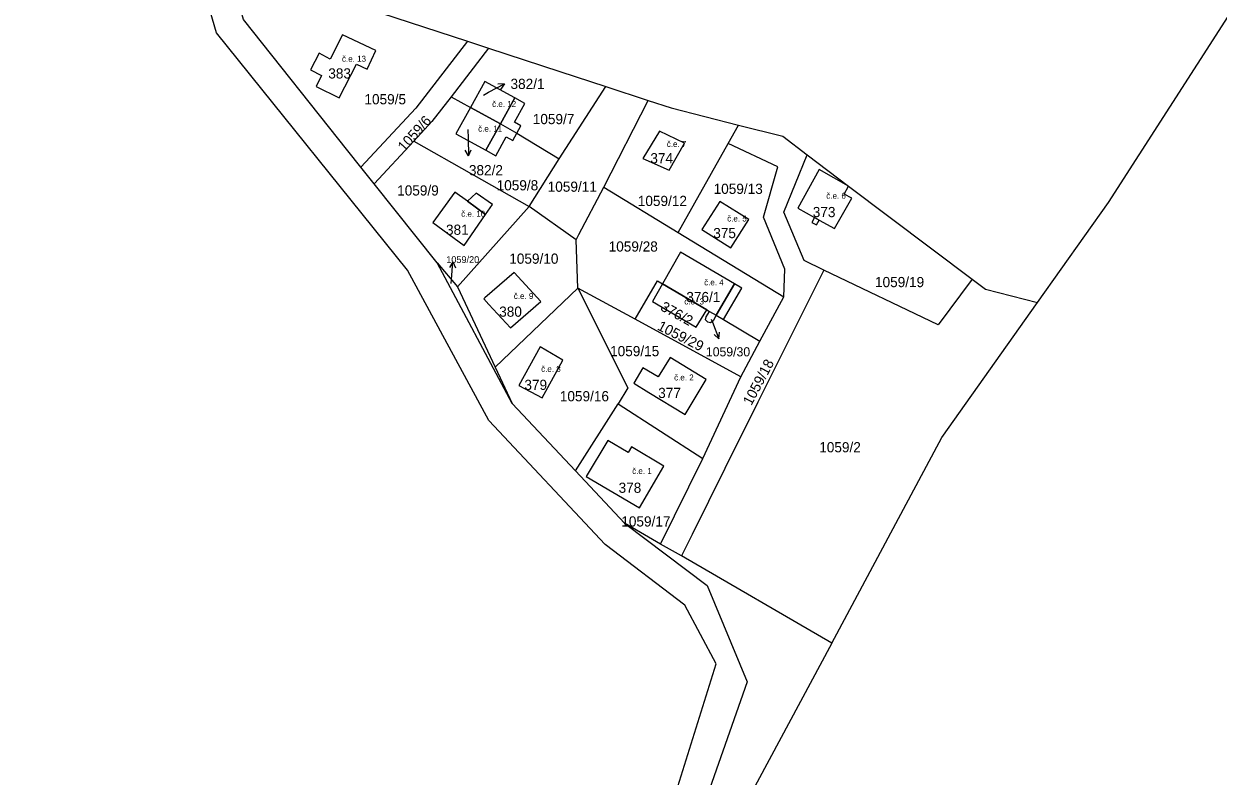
# Model space of a CAD drawing. Extents: x -887272 to -877616, y -1026687 to -1019819.
# Drawn here: x -884874.3 to -884674.7, y -1024745.1 to -1024619.5 of the extents above; entities that cross this region are included whole.
import ezdxf

# ---------------------------------------------------------------- set-up
doc = ezdxf.new("R2010")
doc.units = 0
for name, color, linetype in [('Definiční body', 7, 'Continuous'), ('Hranice parcel', 7, 'Continuous'), ('Parcelní čísla', 7, 'Continuous'), ('Polygon budovy', 7, 'Continuous'), ('Pop  PČ popisy', 7, 'Continuous'), ('Vnitřní kresba', 7, 'Continuous')]:
    doc.layers.add(name, color=color, linetype=linetype)

msp = doc.modelspace()

# ---------------------------------------------------------------- linework, layer by layer
at = {"layer": 'Hranice parcel'}
for p, q in [((-884814.72, -1024617.68), (-884800.18, -1024622.42)), ((-884796.65, -1024623.57), (-884802.91, -1024631.68)), ((-884800.18, -1024622.42), (-884796.65, -1024623.57)), ((-884802.91, -1024631.68), (-884799.68, -1024633.48)), ((-884784.84, -1024642.04), (-884777.08, -1024629.98)), ((-884777.08, -1024629.98), (-884769.96, -1024632.31)), ((-884777.38, -1024646.78), (-884769.96, -1024632.31)), ((-884791.94, -1024637.75), (-884784.84, -1024642.04)), ((-884756.59, -1024639.48), (-884754.87, -1024636.42)), ((-884809.16, -1024639.09), (-884815.78, -1024646.23)), ((-884809.16, -1024639.09), (-884789.89, -1024650)), ((-884764.95, -1024654.33), (-884756.59, -1024639.48)), ((-884815.78, -1024646.23), (-884818, -1024643.45)), ((-884789.89, -1024650), (-884784.84, -1024642.04)), ((-884805.24, -1024659.42), (-884815.78, -1024646.23)), ((-884777.38, -1024646.78), (-884764.95, -1024654.33)), ((-884704.9, -1024666.04), (-884693.07, -1024649.32)), ((-884801.87, -1024663.41), (-884789.89, -1024650)), ((-884782.02, -1024655.56), (-884789.89, -1024650)), ((-884781.74, -1024663.63), (-884782.02, -1024655.56)), ((-884764.95, -1024654.33), (-884747.32, -1024665.08)), ((-884792.7, -1024682.88), (-884805.24, -1024659.42)), ((-884805.24, -1024659.42), (-884801.87, -1024663.41)), ((-884801.87, -1024663.41), (-884795.58, -1024676.85)), ((-884795.58, -1024676.85), (-884781.74, -1024663.63)), ((-884772.16, -1024668.83), (-884781.74, -1024663.63)), ((-884767.59, -1024662.91), (-884760.18, -1024667.27)), ((-884715.82, -1024662.17), (-884713.6, -1024663.84)), ((-884751.3, -1024672.51), (-884747.32, -1024665.08)), ((-884713.6, -1024663.84), (-884704.9, -1024666.04)), ((-884760.18, -1024667.27), (-884759.75, -1024667.52)), ((-884759.75, -1024667.52), (-884758.62, -1024668.17)), ((-884754.48, -1024678.44), (-884772.16, -1024668.83)), ((-884758.62, -1024668.17), (-884757.41, -1024668.87)), ((-884757.41, -1024668.87), (-884751.3, -1024672.51)), ((-884754.48, -1024678.44), (-884751.3, -1024672.51)), ((-884795.58, -1024676.85), (-884792.7, -1024682.88)), ((-884760.84, -1024692.08), (-884754.48, -1024678.44)), ((-884782.13, -1024694.15), (-884792.7, -1024682.88)), ((-884782.13, -1024694.15), (-884774.99, -1024682.96)), ((-884774.99, -1024682.96), (-884760.84, -1024692.08)), ((-884767.91, -1024706.37), (-884760.84, -1024692.08)), ((-884773.92, -1024702.9), (-884782.13, -1024694.15)), ((-884767.91, -1024706.37), (-884773.92, -1024702.9)), ((-884764.44, -1024708.37), (-884767.91, -1024706.37)), ((-884739.28, -1024722.9), (-884764.44, -1024708.37))]:
    msp.add_line(p, q, dxfattribs=at)
for points in [[(-884872.76, -1024922.63), (-884842.58, -1024868.45), (-884811.61, -1024820.67), (-884781.27, -1024777.38), (-884766.7, -1024752.19), (-884758.6, -1024726.39), (-884763.88, -1024716.6), (-884777.17, -1024706.45), (-884796.59, -1024685.75), (-884810.2, -1024660.64), (-884842.12, -1024620.99), (-884851.29, -1024589.53), (-884865.18, -1024571.88), (-884874.31, -1024559.51)], [(-884693.07, -1024649.32), (-884667.92, -1024610.27), (-884632.54, -1024600.92)], [(-884818, -1024643.45), (-884820.18, -1024640.72), (-884837.62, -1024618.78), (-884838.76, -1024614.74)], [(-884818.7, -1024626.24), (-884816.96, -1024627.1), (-884815.47, -1024623.94), (-884821.07, -1024621.37), (-884823.12, -1024625.4), (-884824.97, -1024624.43), (-884826.44, -1024627.21), (-884824.57, -1024628.14), (-884825.47, -1024629.98), (-884821.65, -1024631.89), (-884818.7, -1024626.24)], [(-884800.18, -1024622.42), (-884808.81, -1024633.57), (-884818, -1024643.45)], [(-884796.65, -1024623.57), (-884784.74, -1024627.46), (-884777.08, -1024629.98)], [(-884791.94, -1024637.75), (-884791.26, -1024636.52), (-884792.35, -1024635.93), (-884790.62, -1024632.79), (-884792.28, -1024631.87), (-884797.27, -1024629.12), (-884799.68, -1024633.48)], [(-884802.91, -1024631.68), (-884806.14, -1024635.84), (-884809.16, -1024639.09)], [(-884799.68, -1024633.48), (-884802.1, -1024637.86), (-884797.1, -1024640.61), (-884795.44, -1024641.53), (-884793.7, -1024638.38), (-884792.62, -1024638.98), (-884791.94, -1024637.75)], [(-884799.68, -1024633.48), (-884794.69, -1024636.23), (-884791.94, -1024637.75)], [(-884769.96, -1024632.31), (-884766.16, -1024633.56), (-884754.87, -1024636.42)], [(-884770.9, -1024642.02), (-884766.5, -1024643.96), (-884763.9, -1024639.42), (-884768.1, -1024637.44), (-884770.9, -1024642.02)], [(-884754.87, -1024636.42), (-884747.48, -1024638.28), (-884743.39, -1024641.37)], [(-884747.32, -1024665.08), (-884747.15, -1024660.46), (-884750.73, -1024651.77), (-884748.29, -1024643.38), (-884756.59, -1024639.48)], [(-884740.63, -1024660.62), (-884743.92, -1024659.04), (-884747.32, -1024650.95), (-884743.39, -1024641.37)], [(-884743.39, -1024641.37), (-884736.49, -1024646.62), (-884715.82, -1024662.17)], [(-884736.49, -1024646.62), (-884741.4, -1024643.84), (-884744.98, -1024650.29), (-884742.18, -1024651.85), (-884742.64, -1024652.68), (-884741.87, -1024653.1), (-884741.41, -1024652.27), (-884738.86, -1024653.69), (-884735.97, -1024648.64), (-884737.23, -1024647.93), (-884736.49, -1024646.62)], [(-884796.02, -1024649.68), (-884798.72, -1024647.8), (-884800.16, -1024649.14), (-884802.32, -1024647.64), (-884805.96, -1024652.7), (-884800.72, -1024656.54), (-884797.18, -1024651.34), (-884796.02, -1024649.68)], [(-884782.02, -1024655.56), (-884781.56, -1024654.69), (-884777.38, -1024646.78)], [(-884758.03, -1024649.17), (-884761, -1024653.83), (-884756.17, -1024656.93), (-884753.17, -1024652.21), (-884758.03, -1024649.17)], [(-884757.41, -1024668.87), (-884754.35, -1024663.65), (-884755.54, -1024662.95), (-884764.57, -1024657.65), (-884767.59, -1024662.91)], [(-884797.47, -1024665.45), (-884796.62, -1024666.37), (-884792.98, -1024670.29), (-884787.92, -1024665.87), (-884792.4, -1024661.03), (-884797.28, -1024665.29), (-884797.47, -1024665.45)], [(-884740.63, -1024660.62), (-884746.14, -1024671.66), (-884751.64, -1024682.71), (-884757.15, -1024693.76), (-884762.66, -1024704.8), (-884764.44, -1024708.37)], [(-884715.82, -1024662.17), (-884721.54, -1024669.75), (-884740.63, -1024660.62)], [(-884781.74, -1024663.63), (-884773.36, -1024680.31), (-884774.99, -1024682.96)], [(-884772.16, -1024668.83), (-884768.45, -1024662.41), (-884767.59, -1024662.91)], [(-884767.59, -1024662.91), (-884769.28, -1024665.86), (-884761.94, -1024670.16), (-884760.18, -1024667.27)], [(-884758.62, -1024668.17), (-884759.15, -1024669.08), (-884759.55, -1024669.44), (-884760.04, -1024669.32), (-884760.38, -1024668.96), (-884760.27, -1024668.43), (-884759.75, -1024667.52)], [(-884739.28, -1024722.9), (-884720.9, -1024688.58), (-884704.9, -1024666.04)], [(-884784.22, -1024675.66), (-884788.02, -1024673.46), (-884791.62, -1024679.92), (-884787.7, -1024681.94), (-884784.22, -1024675.66)], [(-884763.83, -1024684.76), (-884760.27, -1024678.9), (-884766.3, -1024675.21), (-884768.29, -1024678.48), (-884770.88, -1024676.97), (-884772.36, -1024679.52), (-884769.86, -1024681.06), (-884763.83, -1024684.76)], [(-884767.37, -1024693.37), (-884772.77, -1024690.17), (-884773.32, -1024691.11), (-884776.75, -1024689.08), (-884780.32, -1024695.1), (-884771.46, -1024700.34), (-884767.37, -1024693.37)], [(-884773.92, -1024702.9), (-884760.13, -1024713.29), (-884753.42, -1024729.37), (-884762.31, -1024754.59), (-884777.4, -1024780.54), (-884807.68, -1024823.76), (-884838.22, -1024870.9), (-884865.47, -1024921.56)], [(-884739.28, -1024722.9), (-884755.02, -1024752.14), (-884789.28, -1024823.84), (-884834.4, -1024887.3), (-884865.47, -1024921.56)]]:
    msp.add_lwpolyline(points, dxfattribs=at)
at = {"layer": 'Polygon budovy'}
for points in [[(-884821.65, -1024631.89), (-884818.7, -1024626.24), (-884816.96, -1024627.1), (-884815.47, -1024623.94), (-884821.07, -1024621.37), (-884823.12, -1024625.4), (-884824.97, -1024624.43), (-884826.44, -1024627.21), (-884824.57, -1024628.14), (-884825.47, -1024629.98)], [(-884799.68, -1024633.48), (-884794.69, -1024636.23), (-884792.28, -1024631.87), (-884797.27, -1024629.12)], [(-884799.68, -1024633.48), (-884802.1, -1024637.86), (-884797.1, -1024640.61), (-884794.69, -1024636.23)], [(-884768.1, -1024637.44), (-884770.9, -1024642.02), (-884766.5, -1024643.96), (-884763.9, -1024639.42)], [(-884741.4, -1024643.84), (-884744.98, -1024650.29), (-884742.18, -1024651.85), (-884741.41, -1024652.27), (-884738.86, -1024653.69), (-884735.97, -1024648.64), (-884737.23, -1024647.93), (-884736.49, -1024646.62)], [(-884797.18, -1024651.34), (-884800.16, -1024649.14), (-884802.32, -1024647.64), (-884805.96, -1024652.7), (-884800.72, -1024656.54)], [(-884756.17, -1024656.93), (-884753.17, -1024652.21), (-884758.03, -1024649.17), (-884761, -1024653.83)], [(-884758.62, -1024668.17), (-884755.54, -1024662.95), (-884764.57, -1024657.65), (-884767.59, -1024662.91), (-884760.18, -1024667.27), (-884759.75, -1024667.52)], [(-884792.4, -1024661.03), (-884797.28, -1024665.29), (-884797.47, -1024665.45), (-884796.62, -1024666.37), (-884792.98, -1024670.29), (-884787.92, -1024665.87)], [(-884761.94, -1024670.16), (-884760.18, -1024667.27), (-884767.59, -1024662.91), (-884769.28, -1024665.86)], [(-884788.02, -1024673.46), (-884791.62, -1024679.92), (-884787.7, -1024681.94), (-884784.22, -1024675.66)], [(-884768.29, -1024678.48), (-884770.88, -1024676.97), (-884772.36, -1024679.52), (-884769.86, -1024681.06), (-884763.83, -1024684.76), (-884760.27, -1024678.9), (-884766.3, -1024675.21)], [(-884776.75, -1024689.08), (-884780.32, -1024695.1), (-884771.46, -1024700.34), (-884767.37, -1024693.37), (-884772.77, -1024690.17), (-884773.32, -1024691.11)]]:
    msp.add_lwpolyline(points, close=True, dxfattribs=at)
at = {"layer": 'Pop  PČ popisy'}
for p, q in [((-884796.64, -1024630.95), (-884793.99, -1024629.54)), ((-884793.99, -1024629.54), (-884795.11, -1024629.57)), ((-884793.99, -1024629.54), (-884794.64, -1024630.45)), ((-884797.53, -1024631.42), (-884796.64, -1024630.95)), ((-884800.12, -1024637.15), (-884800.08, -1024638.58)), ((-884800.08, -1024638.58), (-884800.03, -1024641.58)), ((-884800.03, -1024641.58), (-884800.55, -1024640.59)), ((-884800.03, -1024641.58), (-884799.54, -1024640.57)), ((-884802.62, -1024659.23), (-884803.19, -1024660.19)), ((-884802.83, -1024662.22), (-884802.62, -1024659.23)), ((-884802.62, -1024659.23), (-884802.19, -1024660.26)), ((-884802.88, -1024662.86), (-884802.83, -1024662.22)), ((-884759.43, -1024668.83), (-884759.23, -1024669.33)), ((-884759.23, -1024669.33), (-884758.16, -1024672.13)), ((-884758.16, -1024672.13), (-884758.98, -1024671.38)), ((-884758.16, -1024672.13), (-884758.05, -1024671.02))]:
    msp.add_line(p, q, dxfattribs=at)
at = {"layer": 'Vnitřní kresba'}
for p, q in [((-884792.28, -1024631.87), (-884794.69, -1024636.23)), ((-884794.69, -1024636.23), (-884797.1, -1024640.61)), ((-884800.16, -1024649.14), (-884797.18, -1024651.34)), ((-884741.41, -1024652.27), (-884742.18, -1024651.85)), ((-884755.54, -1024662.95), (-884758.62, -1024668.17))]:
    msp.add_line(p, q, dxfattribs=at)

# ---------------------------------------------------------------- texts
at = {"layer": 'Definiční body'}
for s, p in [('č.e. 13', (-884821.15, -1024625.85)), ('č.e. 12', (-884796.06, -1024633.39)), ('č.e. 11', (-884798.4, -1024637.52)), ('č.e. 7', (-884766.87, -1024640.08)), ('č.e. 6', (-884740.22, -1024648.72)), ('č.e. 10', (-884801.23, -1024651.73)), ('č.e. 5', (-884756.78, -1024652.52)), ('č.e. 4', (-884760.63, -1024663.18)), ('č.e. 9', (-884792.44, -1024665.46)), ('č.e. 3', (-884763.94, -1024666.37)), ('č.e. 8', (-884787.87, -1024677.63)), ('č.e. 2', (-884765.65, -1024679.06)), ('č.e. 1', (-884772.66, -1024694.67))]:
    msp.add_text(s, height=1, dxfattribs=at).set_placement(p)
at = {"layer": 'Parcelní čísla'}
for s, height, p in [('383', 1.7, (-884823.44, -1024628.64)), ('382/1', 1.7, (-884792.99, -1024630.39)), ('1059/5', 1.7, (-884817.4, -1024632.95)), ('1059/7', 1.7, (-884789.27, -1024636.26)), ('374', 1.7, (-884769.62, -1024642.8)), ('382/2', 1.7, (-884799.94, -1024644.8)), ('1059/8', 1.7, (-884795.31, -1024647.32)), ('1059/11', 1.7, (-884786.78, -1024647.55)), ('1059/9', 1.7, (-884811.93, -1024648.18)), ('1059/13', 1.7, (-884759.05, -1024647.91)), ('1059/12', 1.7, (-884771.72, -1024649.93)), ('373', 1.7, (-884742.48, -1024651.79)), ('381', 1.7, (-884803.77, -1024654.74)), ('375', 1.7, (-884759.11, -1024655.3)), ('1059/28', 1.7, (-884776.59, -1024657.54)), ('1059/10', 1.7, (-884793.2, -1024659.57)), ('1059/20', 1.14, (-884803.73, -1024659.45)), ('1059/19', 1.7, (-884732.08, -1024663.48)), ('376/1', 1.7, (-884763.61, -1024665.98)), ('380', 1.7, (-884794.88, -1024668.42)), ('1059/15', 1.7, (-884776.35, -1024675.01)), ('1059/30', 1.53, (-884760.34, -1024675.04)), ('379', 1.7, (-884790.67, -1024680.64)), ('1059/16', 1.7, (-884784.75, -1024682.54)), ('377', 1.7, (-884768.31, -1024681.99)), ('1059/2', 1.7, (-884741.4, -1024691.06)), ('378', 1.7, (-884774.93, -1024697.82)), ('1059/17', 1.7, (-884774.48, -1024703.45))]:
    msp.add_text(s, height=height, dxfattribs=at).set_placement(p)
for s, rotation, p in [('1059/6', 48, (-884810.75, -1024640.96)), ('376/2', 331, (-884768.08, -1024667.25)), ('1059/29', 333, (-884768.58, -1024670.51)), ('1059/18', 62, (-884752.74, -1024683.35))]:
    msp.add_text(s, height=1.7, rotation=rotation, dxfattribs=at).set_placement(p)

doc.saveas('drawing.dxf')
